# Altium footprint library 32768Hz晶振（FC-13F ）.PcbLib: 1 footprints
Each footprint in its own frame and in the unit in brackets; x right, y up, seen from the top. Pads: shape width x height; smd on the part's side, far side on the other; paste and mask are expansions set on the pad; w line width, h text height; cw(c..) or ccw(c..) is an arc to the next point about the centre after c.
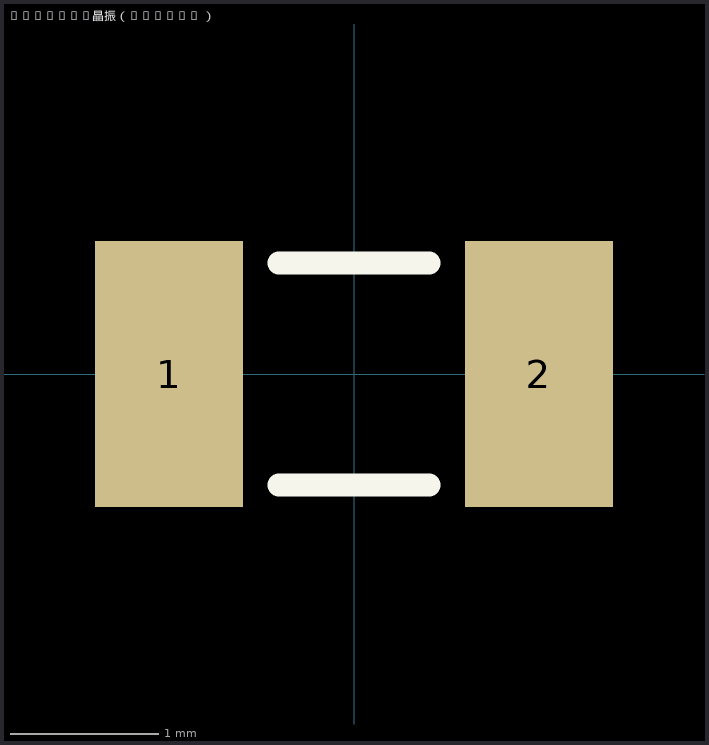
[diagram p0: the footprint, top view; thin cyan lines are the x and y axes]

## 32768Hz晶振（FC-13F ） [mm] "32768Hz晶振（FC-13F ）"
pads (2):
  rect 1x1.8 smd: 1(-1.25,0) 2(1.25,0)
Top Overlay:
  lines w0.152: -0.508,-0.75 0.508,-0.75 ; -0.508,0.75 0.508,0.75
